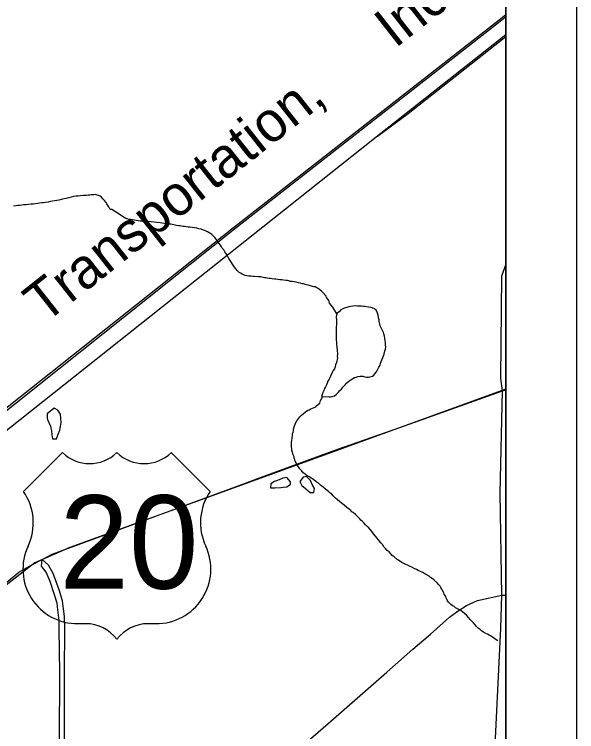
# Model space of a CAD drawing. Extents: x 0 to 34, y 0 to 22.
# Drawn here: x 8.206 to 9, y 15.792 to 16.806 of the extents above; entities that cross this region are included whole.
import ezdxf

# ---------------------------------------------------------------- set-up
doc = ezdxf.new("R2010")
doc.units = 0
for name, color, linetype in [('GM_X_City_Street', 7, 'Continuous'), ('GM_X_Corporation', 7, 'Continuous'), ('GM_X_Minor_Lake', 7, 'Continuous'), ('GM_X_Minor_River', 7, 'Continuous'), ('GM_X_Rail_Line', 7, 'Continuous'), ('GM_X_Rail_Line_Text', 7, 'Continuous'), ('GM_X_State_Route', 7, 'Continuous'), ('GM_X_US_Location', 7, 'Continuous'), ('GM_X_US_Route', 7, 'Continuous'), ('GM_X_US_Shield', 7, 'Continuous'), ('SH_Data', 7, 'Continuous')]:
    doc.layers.add(name, color=color, linetype=linetype)

msp = doc.modelspace()

# ---------------------------------------------------------------- linework, layer by layer
at = {"layer": 'GM_X_City_Street'}
for points in [[(8.8954, 16.2736), (8.8928, 16.2918), (8.8944, 16.4361), (8.9001, 16.4516)], [(8.8348, 14.6931), (8.847, 14.7173), (8.8504, 14.7243), (8.8514, 14.7269), (8.8527, 14.7302), (8.8538, 14.7327), (8.8625, 14.8936), (8.8639, 14.9516), (8.8651, 14.996), (8.8669, 15.2902), (8.8834, 15.7442), (8.893, 15.9388), (8.8945, 15.9852), (8.8918, 16.1294), (8.8954, 16.2736)], [(8.2705, 15.4738), (8.2704, 15.6042), (8.2712, 15.6272), (8.2708, 15.7322), (8.27, 15.7806), (8.2704, 15.8758), (8.2693, 15.937), (8.2693, 15.9495), (8.2677, 15.9644), (8.2665, 15.9737), (8.2631, 15.9856), (8.2569, 16.0043), (8.251, 16.0178), (8.2444, 16.0264), (8.2453, 16.0355)], [(8.2796, 15.4817), (8.2786, 15.5354), (8.2781, 15.6123), (8.2781, 15.6575), (8.2774, 15.7643), (8.277, 15.7816), (8.2772, 15.8751), (8.2774, 15.9392), (8.2768, 15.955), (8.2758, 15.9659), (8.274, 15.9773), (8.2695, 15.9929), (8.2608, 16.0159), (8.2542, 16.0275), (8.2453, 16.0355)]]:
    msp.add_lwpolyline(points, dxfattribs=at)
at = {"layer": 'GM_X_Corporation'}
for points in [[(2.1001, 14.1001), (8.9001, 14.1001), (8.9001, 20.7375)], [(2.1001, 14.1001), (8.9001, 14.1001), (8.9001, 20.7375)], [(6.9579, 18.132), (6.9502, 17.5872), (6.9468, 17.2888), (6.9413, 17.0038), (6.9287, 16.435), (6.9142, 15.8181), (6.9021, 15.2678), (6.9994, 15.3186), (7.0214, 15.1124), (7.0221, 15.106), (7.0848, 15.1475), (7.2625, 14.8601), (7.3892, 14.8475), (7.3905, 14.7219), (7.3907, 14.701), (7.7494, 14.7173), (7.8563, 14.7146), (7.8592, 14.6786), (7.9049, 14.6645), (8.8347, 14.6937), (8.9001, 14.6961), (8.9001, 19.9513)]]:
    msp.add_lwpolyline(points, dxfattribs=at)
at = {"layer": 'GM_X_Minor_Lake'}
for points in [[(8.7282, 16.3258), (8.7283, 16.3263), (8.7294, 16.3301), (8.73, 16.3328), (8.7304, 16.3355), (8.7303, 16.3382), (8.7302, 16.3416), (8.7297, 16.3446), (8.7293, 16.348), (8.7288, 16.3511), (8.728, 16.3541), (8.7272, 16.356), (8.7264, 16.3579), (8.7255, 16.3598), (8.7243, 16.362), (8.7235, 16.3639), (8.7227, 16.3658), (8.7223, 16.368), (8.7214, 16.3718), (8.7214, 16.3741), (8.7205, 16.3771), (8.7197, 16.3813), (8.7188, 16.3836), (8.7168, 16.3877), (8.7145, 16.3896), (8.7114, 16.391), (8.7095, 16.3913), (8.7061, 16.392), (8.7034, 16.3923), (8.7015, 16.3927), (8.6992, 16.393), (8.6965, 16.3933), (8.6934, 16.3936), (8.6904, 16.3935), (8.6873, 16.3938), (8.6839, 16.3933), (8.6809, 16.3929), (8.6782, 16.3924), (8.6711, 16.39), (8.6692, 16.3892), (8.6673, 16.388), (8.6647, 16.3856), (8.6617, 16.3833), (8.6607, 16.379), (8.6607, 16.3768), (8.6608, 16.3745), (8.6609, 16.3714), (8.6609, 16.3691), (8.661, 16.3669), (8.6607, 16.3642), (8.6607, 16.3619), (8.6604, 16.3589), (8.6605, 16.3566), (8.6606, 16.3539), (8.6606, 16.3516), (8.6607, 16.349), (8.6607, 16.3471), (8.6609, 16.341), (8.6609, 16.3387), (8.6614, 16.3364), (8.6614, 16.3345), (8.6619, 16.3322), (8.6619, 16.3296), (8.6624, 16.3269), (8.6624, 16.325), (8.6621, 16.3227), (8.6622, 16.3204), (8.6608, 16.3139), (8.6598, 16.3105), (8.6591, 16.3078), (8.658, 16.3051), (8.6565, 16.3024), (8.6547, 16.2997), (8.6529, 16.2954), (8.6518, 16.2924), (8.6508, 16.2901), (8.6489, 16.2877), (8.6479, 16.2847), (8.6468, 16.2823), (8.6453, 16.2796), (8.6442, 16.277), (8.6435, 16.275), (8.6417, 16.2716), (8.641, 16.2696), (8.6403, 16.2673), (8.64, 16.2658)], [(8.6983, 16.2943), (8.701, 16.2936), (8.7033, 16.2933), (8.7063, 16.293), (8.7097, 16.2939), (8.7116, 16.2947), (8.7135, 16.2959), (8.7149, 16.2978), (8.7172, 16.3001), (8.719, 16.3036), (8.7208, 16.3071), (8.7226, 16.3102), (8.7233, 16.3129), (8.7282, 16.3258)], [(8.64, 16.2658), (8.6506, 16.2653), (8.6525, 16.2654), (8.6548, 16.2658), (8.6582, 16.2666), (8.6612, 16.269), (8.6634, 16.2713), (8.6656, 16.2741), (8.6679, 16.2764), (8.6701, 16.2791), (8.6731, 16.2823), (8.6757, 16.285), (8.6783, 16.2873), (8.6813, 16.2893), (8.6839, 16.2913), (8.6865, 16.2925), (8.6888, 16.2933), (8.691, 16.2941), (8.6945, 16.2946), (8.6964, 16.2947), (8.6983, 16.2943)], [(8.2625, 16.2495), (8.2523, 16.2411), (8.2523, 16.2355), (8.2529, 16.2333)], [(8.2659, 16.206), (8.2681, 16.2128), (8.2703, 16.2182), (8.2714, 16.2235), (8.2721, 16.2292), (8.2717, 16.2349), (8.2712, 16.241), (8.2678, 16.2466), (8.2625, 16.2495)], [(8.2529, 16.2333), (8.2574, 16.2241), (8.2586, 16.2173), (8.259, 16.2116), (8.2602, 16.2059), (8.2659, 16.206)], [(8.5962, 16.1454), (8.591, 16.1513), (8.5853, 16.1505), (8.5799, 16.1483)], [(8.6125, 16.1501), (8.6091, 16.1457), (8.6122, 16.1401), (8.6174, 16.1357)], [(8.614, 16.152), (8.6125, 16.1501)], [(8.629, 16.1304), (8.6297, 16.1361), (8.6267, 16.1417), (8.6243, 16.1474), (8.6186, 16.1527), (8.614, 16.152)], [(8.5683, 16.1427), (8.568, 16.137), (8.5741, 16.1367), (8.5824, 16.1375)], [(8.5799, 16.1483), (8.5736, 16.1458), (8.5683, 16.1427)], [(8.5824, 16.1375), (8.5855, 16.1379), (8.5908, 16.1384), (8.596, 16.1422), (8.5962, 16.1454)], [(8.6174, 16.1357), (8.6237, 16.1303), (8.629, 16.1304)]]:
    msp.add_lwpolyline(points, dxfattribs=at)
at = {"layer": 'GM_X_Minor_River'}
for points in [[(8.4208, 16.5096), (8.4181, 16.5103), (8.415, 16.5106), (8.412, 16.5109), (8.4074, 16.5116), (8.4036, 16.5119), (8.3994, 16.5125), (8.3955, 16.5128), (8.3921, 16.5127), (8.3891, 16.513), (8.3864, 16.5133), (8.3837, 16.5136), (8.381, 16.514), (8.3784, 16.5143), (8.3757, 16.515), (8.373, 16.5153), (8.3703, 16.5156), (8.368, 16.5159), (8.3653, 16.5166), (8.3634, 16.5173), (8.3611, 16.5188), (8.3475, 16.5276), (8.3437, 16.5298), (8.3414, 16.5301), (8.3398, 16.5335), (8.3386, 16.5353), (8.3366, 16.538), (8.3358, 16.5398), (8.3334, 16.5425), (8.3311, 16.5451), (8.3291, 16.5473), (8.3272, 16.5488), (8.3249, 16.5495), (8.323, 16.5502), (8.3203, 16.5509), (8.3184, 16.5508), (8.3153, 16.5507), (8.3127, 16.5503), (8.3104, 16.5502), (8.3081, 16.5498), (8.3051, 16.5497), (8.3032, 16.5497), (8.2997, 16.5492), (8.2963, 16.5487), (8.2929, 16.5487), (8.2895, 16.5482), (8.2865, 16.5473), (8.2831, 16.5465), (8.2793, 16.5453), (8.274, 16.5444), (8.269, 16.5431), (8.2573, 16.5413), (8.2539, 16.5404), (8.2501, 16.5399), (8.247, 16.5395), (8.2448, 16.5394), (8.2417, 16.539), (8.2391, 16.5385), (8.236, 16.5381), (8.2326, 16.5376), (8.2296, 16.5375), (8.2262, 16.5371), (8.2227, 16.5366), (8.2197, 16.5365), (8.2167, 16.536), (8.2136, 16.5356), (8.211, 16.5355), (8.2087, 16.5351), (8.2049, 16.5346)], [(8.6615, 16.3825), (8.6558, 16.3919), (8.6534, 16.3949), (8.6511, 16.3975), (8.6502, 16.4012), (8.6486, 16.4035), (8.647, 16.4057), (8.6462, 16.4076), (8.6419, 16.4125), (8.64, 16.4147), (8.6376, 16.4165), (8.6353, 16.4184), (8.6334, 16.4195), (8.631, 16.4206), (8.6291, 16.4209), (8.6272, 16.4212), (8.6245, 16.4223), (8.6215, 16.423), (8.6184, 16.4237), (8.6146, 16.4247), (8.6126, 16.425), (8.6103, 16.4257), (8.6073, 16.4264), (8.6042, 16.4271), (8.6011, 16.4278), (8.5985, 16.4281), (8.5958, 16.4284), (8.5939, 16.4291), (8.5916, 16.4295), (8.5897, 16.4298), (8.5862, 16.4301), (8.5836, 16.4304), (8.5809, 16.4307), (8.5782, 16.431), (8.5755, 16.4313), (8.5736, 16.4317), (8.5702, 16.432), (8.5679, 16.4323), (8.566, 16.4326), (8.5633, 16.4329), (8.5614, 16.4333), (8.5595, 16.4336), (8.5576, 16.4339), (8.5541, 16.4346), (8.5511, 16.4349), (8.5453, 16.4355), (8.5434, 16.4355), (8.5404, 16.4358), (8.5373, 16.4357), (8.5346, 16.436), (8.532, 16.4367), (8.53, 16.4378), (8.5277, 16.4385), (8.5254, 16.44), (8.5235, 16.441), (8.5207, 16.4436), (8.5188, 16.4459), (8.5176, 16.4478), (8.516, 16.45), (8.5144, 16.4526), (8.5128, 16.4552), (8.5108, 16.4579), (8.5092, 16.4609), (8.5077, 16.4635), (8.5061, 16.4665), (8.5033, 16.4699), (8.5017, 16.4729), (8.4997, 16.4751), (8.4985, 16.477), (8.497, 16.4796), (8.4954, 16.4818), (8.4938, 16.4841), (8.4926, 16.4863), (8.491, 16.4882), (8.4891, 16.4904), (8.4875, 16.4923), (8.4851, 16.4945), (8.4832, 16.496), (8.4813, 16.4971), (8.479, 16.4982), (8.477, 16.4993), (8.4736, 16.5007), (8.4716, 16.5014), (8.4697, 16.5021), (8.4667, 16.5028), (8.4636, 16.5035), (8.454, 16.5048), (8.4514, 16.5051), (8.4487, 16.5054), (8.4464, 16.5057), (8.4445, 16.5061), (8.4422, 16.5064), (8.4403, 16.5067), (8.438, 16.507), (8.4349, 16.5073), (8.4315, 16.5084), (8.4292, 16.5087), (8.4269, 16.509), (8.425, 16.509), (8.4227, 16.5093), (8.4208, 16.5096)], [(8.6499, 16.1316), (8.6479, 16.1331), (8.6456, 16.1349), (8.6421, 16.1379), (8.6401, 16.1394), (8.6382, 16.1408), (8.6355, 16.1434), (8.6335, 16.1442), (8.6312, 16.146), (8.6269, 16.1493), (8.625, 16.1504), (8.6227, 16.1523), (8.62, 16.1533), (8.6169, 16.1559), (8.6141, 16.1581), (8.6114, 16.1611), (8.609, 16.1637), (8.6075, 16.1663), (8.6051, 16.1697), (8.6039, 16.172), (8.6027, 16.1746), (8.6022, 16.1765), (8.6014, 16.1788), (8.601, 16.1806), (8.5998, 16.1833), (8.5989, 16.1867), (8.5981, 16.1901), (8.598, 16.1924), (8.5976, 16.1946), (8.5975, 16.1966), (8.5975, 16.1992), (8.5974, 16.2015), (8.5977, 16.2038), (8.5987, 16.2114), (8.599, 16.2133), (8.5997, 16.2153), (8.6001, 16.2172), (8.6004, 16.2199), (8.6014, 16.2229), (8.6021, 16.2252), (8.6032, 16.2283), (8.605, 16.2314), (8.6076, 16.2353), (8.6094, 16.2372), (8.6117, 16.2396), (8.6139, 16.2415), (8.6173, 16.2443), (8.6203, 16.2463), (8.6222, 16.2471), (8.624, 16.2479), (8.627, 16.2495), (8.6293, 16.2503), (8.6319, 16.2511), (8.6334, 16.2531), (8.6357, 16.255), (8.6375, 16.2566), (8.6386, 16.26), (8.6404, 16.2635), (8.6418, 16.2657)], [(8.8888, 15.9207), (8.8865, 15.9221), (8.8845, 15.9236), (8.8814, 15.9258), (8.8783, 15.928), (8.8764, 15.9287), (8.8741, 15.9302), (8.8718, 15.9313), (8.8687, 15.9331), (8.866, 15.9346), (8.8636, 15.9368), (8.8609, 15.9386), (8.8586, 15.9412), (8.8566, 15.9435), (8.8542, 15.9461), (8.8515, 15.949), (8.8499, 15.9509), (8.8472, 15.9539), (8.8444, 15.9569), (8.8417, 15.9595), (8.839, 15.9617), (8.8363, 15.9635), (8.8336, 15.965), (8.8316, 15.966), (8.8289, 15.9675), (8.827, 15.969), (8.8243, 15.9704), (8.8223, 15.9719), (8.8192, 15.9753), (8.8172, 15.9782), (8.8164, 15.9805), (8.8152, 15.9824), (8.8144, 15.9846), (8.8132, 15.9865), (8.8124, 15.9884), (8.8108, 15.9918), (8.8096, 15.9937), (8.8084, 15.9959), (8.8072, 15.9978), (8.8056, 16), (8.8033, 16.0026), (8.7986, 16.0067), (8.7959, 16.0089), (8.7939, 16.0104), (8.7916, 16.0119), (8.7877, 16.0144), (8.7858, 16.0155), (8.7827, 16.0173), (8.7796, 16.0188), (8.7765, 16.0202), (8.7738, 16.0213), (8.7707, 16.0231), (8.7673, 16.025), (8.7642, 16.0264), (8.7611, 16.0275), (8.7588, 16.0285), (8.7569, 16.0296), (8.7534, 16.0315), (8.7503, 16.0333), (8.7483, 16.0348), (8.7464, 16.0358), (8.7425, 16.0396), (8.7398, 16.0414), (8.7375, 16.0436), (8.7351, 16.0462), (8.7324, 16.0484), (8.7296, 16.0514), (8.7277, 16.0536), (8.7257, 16.0566), (8.7237, 16.0593), (8.7218, 16.0615), (8.7202, 16.0634), (8.7178, 16.0663), (8.7162, 16.0686), (8.7131, 16.0719), (8.7115, 16.0746), (8.7088, 16.0775), (8.7064, 16.0801), (8.7045, 16.082), (8.7021, 16.0846), (8.6998, 16.0872), (8.6978, 16.0894), (8.6955, 16.0913), (8.6939, 16.0931), (8.6904, 16.0961), (8.6877, 16.0991), (8.6845, 16.102), (8.6826, 16.1031), (8.681, 16.105), (8.6787, 16.1065), (8.6756, 16.1091), (8.6717, 16.1124), (8.6698, 16.1139), (8.6678, 16.1157), (8.6659, 16.1172), (8.662, 16.1205), (8.6596, 16.1224), (8.6565, 16.1257), (8.6542, 16.1279), (8.6518, 16.1298), (8.6499, 16.1316)]]:
    msp.add_lwpolyline(points, dxfattribs=at)
at = {"layer": 'GM_X_Rail_Line'}
for points in [[(6.6237, 15.1553), (6.6743, 15.1672), (6.7378, 15.1849), (6.814, 15.2116), (6.891, 15.2462), (6.9588, 15.2844), (7.0054, 15.3121), (7.0582, 15.3501), (7.2871, 15.5311), (7.6599, 15.8282), (8.0769, 16.1566), (8.5157, 16.5045), (8.8904, 16.7977), (8.9001, 16.8054)], [(6.6242, 15.153), (6.6748, 15.1649), (6.7385, 15.1827), (6.8148, 15.2095), (6.8921, 15.2442), (6.96, 15.2825), (7.0098, 15.3111), (7.0632, 15.3489), (7.289, 15.5277), (7.6646, 15.8264), (8.083, 16.1569), (8.5171, 16.5027), (8.8918, 16.7959), (8.9001, 16.8025)], [(6.6266, 14.9819), (6.6396, 14.9896), (6.6528, 14.9982), (6.6734, 15.0126), (6.6898, 15.0251), (7.0335, 15.2973), (7.1242, 15.3694), (7.23, 15.4532), (7.3475, 15.5463), (7.4216, 15.6051), (7.5158, 15.6797), (7.6294, 15.7697), (7.7359, 15.8545), (8.0929, 16.1372), (8.3833, 16.3675), (8.7147, 16.6305), (8.9001, 16.7773)], [(8.7188, 16.6337), (8.7623, 16.6653), (8.9001, 16.7743)], [(8.9001, 16.2761), (8.2846, 16.0525), (8.2351, 16.0308), (7.6286, 15.5585), (7.3522, 15.3285), (6.9809, 15.0864), (6.9468, 15.0706), (6.8568, 15.011), (6.7801, 14.9477), (6.7423, 14.9258), (6.4831, 14.826), (6.4161, 14.8066), (6.3197, 14.7585), (6.2075, 14.6898), (6.1801, 14.6771), (6.15, 14.6743), (6.1143, 14.6764), (6.1057, 14.6241), (6.068, 14.5413), (6.0488, 14.5029)]]:
    msp.add_lwpolyline(points, dxfattribs=at)
at = {"layer": 'GM_X_State_Route'}
msp.add_line((8.8945, 15.9852), (8.9001, 15.9854), dxfattribs=at)
for points in [[(8.7321, 15.8767), (8.7687, 15.9088), (8.7938, 15.9301), (8.8207, 15.954), (8.8329, 15.9631), (8.8444, 15.9704), (8.86, 15.9776), (8.8945, 15.9852)], [(7.7115, 14.9873), (7.7849, 15.0518), (7.8996, 15.153), (7.9364, 15.1832), (7.997, 15.2378), (8.0037, 15.2425), (8.0208, 15.2579), (8.0874, 15.3152), (8.2772, 15.4796), (8.4913, 15.667), (8.6494, 15.8039), (8.7321, 15.8767)]]:
    msp.add_lwpolyline(points, dxfattribs=at)
at = {"layer": 'GM_X_US_Route'}
msp.add_line((8.8954, 16.2736), (8.9001, 16.2753), dxfattribs=at)
for points in [[(8.5485, 16.1494), (8.6614, 16.1908), (8.7504, 16.2222), (8.8954, 16.2736)], [(8.1837, 15.9943), (8.2126, 16.0175), (8.2317, 16.0287), (8.2453, 16.0355), (8.2595, 16.0432), (8.5326, 16.1436), (8.5485, 16.1494)]]:
    msp.add_lwpolyline(points, dxfattribs=at)
at = {"layer": 'GM_X_US_Shield'}
for p, q in [((8.274, 16.1867), (8.2191, 16.1317)), ((8.4828, 16.1317), (8.4278, 16.1867)), ((8.296, 15.945), (8.307, 15.945)), ((8.3949, 15.945), (8.4059, 15.945))]:
    msp.add_line(p, q, dxfattribs=at)
for centre, radius, start, end in [((8.3125, 16.2259), 0.0549, 225.573, 314.427), ((8.3894, 16.2259), 0.0549, 225.573, 314.427), ((8.1561, 16.0876), 0.0769, 334.5471, 35.0009), ((8.5458, 16.0876), 0.0769, 144.9991, 205.4529), ((8.2952, 16.0219), 0.0769, 154.8319, 270.6383), ((8.4067, 16.0219), 0.0769, 269.3617, 25.1681), ((8.307, 15.89), 0.0549, 36.8699, 90), ((8.3949, 15.89), 0.0549, 90, 143.1301)]:
    msp.add_arc(centre, radius, start, end, dxfattribs=at)
at = {"layer": 'SH_Data'}
for p, q in [((9, 21), (9, 14)), ((8.9, 20.9), (8.9, 14.1))]:
    msp.add_line(p, q, dxfattribs=at)

# ---------------------------------------------------------------- texts
at = {"layer": 'GM_X_Rail_Line_Text'}
for s, height, rotation, p in [('Inc.', 0.05663, 38.0239, (8.7436, 16.7567)), ('Transportation,', 0.056629, 38.2593, (8.2487, 16.3677))]:
    msp.add_text(s, height=height, rotation=rotation, dxfattribs=at).set_placement(p)
at = {"layer": 'GM_X_US_Location'}
for s in ['0', '/']:
    msp.add_text(s, height=0.000189, dxfattribs=at).set_placement((8.3509, 16.0593))
msp.add_text('20', height=0.000189, rotation=0, dxfattribs=at).set_placement((8.3118, 16.0201))
at = {"layer": 'GM_X_US_Shield'}
msp.add_text('20', height=0.13184, dxfattribs=at).set_placement((8.27, 15.9944))

doc.saveas('drawing.dxf')
